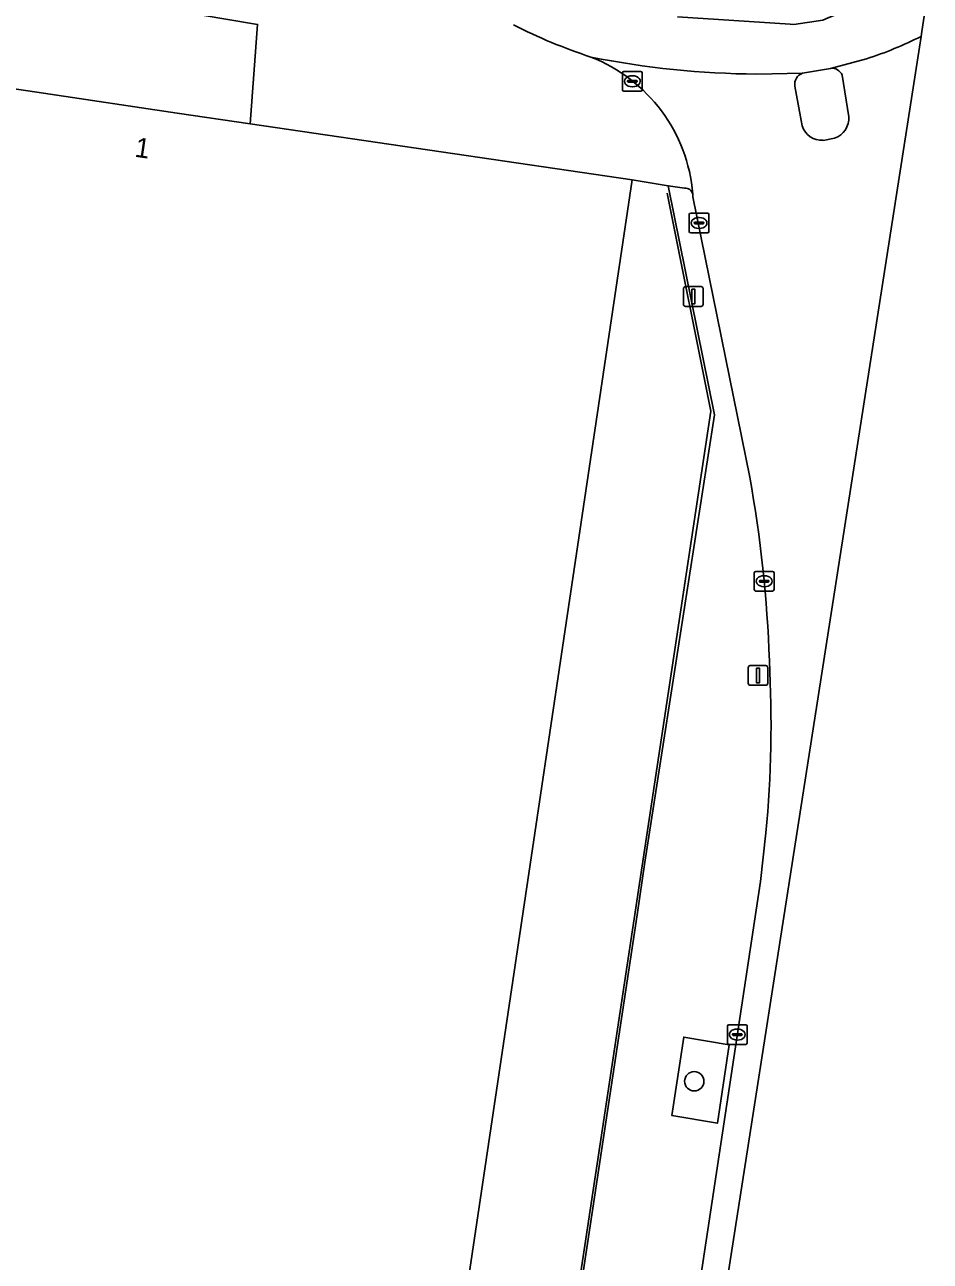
# Model space of a CAD drawing. Extents: x 163008 to 163854, y 382777 to 383982.
# Drawn here: x 163664.1 to 163710.1, y 382884.8 to 382947.5 of the extents above; entities that cross this region are included whole.
import ezdxf

# ---------------------------------------------------------------- set-up
doc = ezdxf.new("R2010")
doc.units = 0
for name, color, linetype in [('IMGEO_Boom', 7, 'Continuous'), ('IMGEO_Erf', 7, 'Continuous'), ('IMGEO_Fietspad_gesloten', 7, 'Continuous'), ('IMGEO_Groenvoorziening', 7, 'Continuous'), ('IMGEO_Hek', 7, 'Continuous'), ('IMGEO_Kolk', 7, 'Continuous'), ('IMGEO_Lichtmast', 7, 'Continuous'), ('IMGEO_Pand', 7, 'Continuous'), ('IMGEO_Pand_nummerreeks', 7, 'Continuous'), ('IMGEO_Rijbaan_lokaal_gesloten', 7, 'Continuous'), ('IMGEO_Verkeerseiland_gesloten', 7, 'Continuous'), ('IMGEO_Voetpad_open', 7, 'Continuous')]:
    doc.layers.add(name, color=color, linetype=linetype)

msp = doc.modelspace()

# ---------------------------------------------------------------- linework, layer by layer
at = {"layer": 'IMGEO_Boom'}
msp.add_circle((163698.093, 382893.932), 0.489, dxfattribs=at)
at = {"layer": 'IMGEO_Erf'}
msp.add_lwpolyline([(163660.069, 382944.782), (163665.094, 382944.032), (163671.874, 382943.02), (163675.573, 382942.478), (163675.95, 382947.517), (163662.801, 382949.742)], dxfattribs=at)
msp.add_lwpolyline([(163695.192, 382902.377), (163695.593, 382905.038), (163699.126, 382927.727), (163696.771, 382939.336), (163694.944, 382939.641), (163686.07, 382880.075), (163680.173, 382841.91), (163682.212, 382846.916), (163682.423, 382846.829), (163682.563, 382846.772), (163689.287, 382863.234)], close=True, dxfattribs=at)
at = {"layer": 'IMGEO_Fietspad_gesloten'}
for points in [[(163709.595, 382946.913), (163709.634, 382947.163), (163710.061, 382949.969), (163710.061, 382949.969), (163709.813, 382949.868), (163704.879, 382947.85), (163704.615, 382947.741), (163703.136, 382947.515), (163702.959, 382947.527), (163697.238, 382947.909)], [(163701.26, 382945.001), (163703.586, 382945.042), (163705.005, 382945.29), (163706.832, 382945.777)]]:
    msp.add_lwpolyline(points, dxfattribs=at)
for centre, radius, start, end in [((163701.319, 382971.705), 27.193, 242.87549, 251.85164), ((163701.11, 382963.624), 18.742, 287.77776, 296.92025), ((163701.592, 382989.658), 44.659, 258.70975, 269.57373)]:
    msp.add_arc(centre, radius, start, end, dxfattribs=at)
at = {"layer": 'IMGEO_Groenvoorziening'}
msp.add_lwpolyline([(163699.86, 382895.783), (163697.558, 382896.177), (163696.959, 382892.195), (163699.266, 382891.807)], close=True, dxfattribs=at)
at = {"layer": 'IMGEO_Hek'}
msp.add_lwpolyline([(163696.717, 382938.956), (163698.941, 382927.911), (163689.192, 382863.442), (163682.423, 382846.829)], dxfattribs=at)
at = {"layer": 'IMGEO_Kolk'}
for p, q in [((163694.453, 382944.208), (163694.453, 382945.06)), ((163694.528, 382945.134), (163695.38, 382945.134)), ((163694.755, 382944.677), (163695.153, 382944.677)), ((163694.941, 382944.914), (163694.966, 382944.914)), ((163695.454, 382945.06), (163695.454, 382944.208)), ((163695.38, 382944.134), (163694.528, 382944.134)), ((163694.712, 382944.628), (163694.712, 382944.64)), ((163695.15, 382944.591), (163694.752, 382944.591)), ((163694.964, 382944.354), (163694.939, 382944.354)), ((163695.196, 382944.64), (163695.196, 382944.628)), ((163697.837, 382937.024), (163697.837, 382937.876)), ((163697.912, 382937.95), (163698.764, 382937.95)), ((163698.838, 382937.876), (163698.838, 382937.024)), ((163698.096, 382937.444), (163698.096, 382937.456)), ((163698.534, 382937.407), (163698.136, 382937.407)), ((163698.139, 382937.493), (163698.537, 382937.493)), ((163698.348, 382937.17), (163698.323, 382937.17)), ((163698.325, 382937.73), (163698.35, 382937.73)), ((163698.58, 382937.456), (163698.58, 382937.444)), ((163698.764, 382936.95), (163697.912, 382936.95)), ((163701.139, 382918.861), (163701.139, 382919.713)), ((163701.214, 382919.787), (163702.066, 382919.787)), ((163702.14, 382919.713), (163702.14, 382918.861)), ((163701.398, 382919.281), (163701.398, 382919.293)), ((163701.836, 382919.244), (163701.438, 382919.244)), ((163701.441, 382919.33), (163701.839, 382919.33)), ((163701.65, 382919.007), (163701.625, 382919.007)), ((163701.627, 382919.567), (163701.652, 382919.567)), ((163701.882, 382919.293), (163701.882, 382919.281)), ((163702.066, 382918.787), (163701.214, 382918.787)), ((163699.775, 382895.875), (163699.775, 382896.727)), ((163699.85, 382896.801), (163700.702, 382896.801)), ((163700.263, 382896.581), (163700.288, 382896.581)), ((163700.776, 382896.727), (163700.776, 382895.875)), ((163700.702, 382895.801), (163699.85, 382895.801)), ((163700.034, 382896.295), (163700.034, 382896.307)), ((163700.472, 382896.258), (163700.074, 382896.258)), ((163700.077, 382896.344), (163700.475, 382896.344)), ((163700.286, 382896.021), (163700.261, 382896.021)), ((163700.518, 382896.307), (163700.518, 382896.295))]:
    msp.add_line(p, q, dxfattribs=at)
for points in [[(163694.453, 382944.208), (163694.453, 382945.06)], [(163694.528, 382945.134), (163695.38, 382945.134)], [(163695.454, 382945.06), (163695.454, 382944.208)], [(163695.38, 382944.134), (163694.528, 382944.134)], [(163697.837, 382937.024), (163697.837, 382937.876)], [(163697.912, 382937.95), (163698.764, 382937.95)], [(163698.838, 382937.876), (163698.838, 382937.024)], [(163698.764, 382936.95), (163697.912, 382936.95)], [(163701.139, 382918.861), (163701.139, 382919.713)], [(163701.214, 382919.787), (163702.066, 382919.787)], [(163702.14, 382919.713), (163702.14, 382918.861)], [(163702.066, 382918.787), (163701.214, 382918.787)], [(163699.775, 382895.875), (163699.775, 382896.727)], [(163699.85, 382896.801), (163700.702, 382896.801)], [(163700.776, 382896.727), (163700.776, 382895.875)], [(163700.702, 382895.801), (163699.85, 382895.801)]]:
    msp.add_lwpolyline(points, dxfattribs=at)
for centre, radius, start, end in [((163694.53, 382945.058), 0.0765, 91.55205, 178.44795), ((163694.53, 382945.058), 0.0765, 91.55205, 178.44795), ((163694.752, 382944.637), 0.0403, 85.87752, 175.75265), ((163695.157, 382944.639), 0.0386, 1.73085, 96.63898), ((163695.378, 382945.058), 0.0765, 1.55205, 88.44795), ((163695.378, 382945.058), 0.0765, 1.55205, 88.44795), ((163694.53, 382944.21), 0.0765, 181.55205, 268.44795), ((163694.53, 382944.21), 0.0765, 181.55205, 268.44795), ((163694.749, 382944.627), 0.0366, 178.93798, 274.71019), ((163695.153, 382944.634), 0.043, 264.86636, 352.45326), ((163695.378, 382944.21), 0.0765, 271.55205, 358.44795), ((163695.378, 382944.21), 0.0765, 271.55205, 358.44795), ((163697.914, 382937.874), 0.0765, 91.55205, 178.44795), ((163697.914, 382937.874), 0.0765, 91.55205, 178.44795), ((163698.762, 382937.874), 0.0765, 1.55205, 88.44795), ((163698.762, 382937.874), 0.0765, 1.55205, 88.44795), ((163698.136, 382937.453), 0.0403, 85.87752, 175.75265), ((163698.133, 382937.443), 0.0366, 178.93798, 274.71019), ((163698.537, 382937.45), 0.043, 264.86636, 352.45326), ((163698.541, 382937.455), 0.0386, 1.73085, 96.63898), ((163697.914, 382937.026), 0.0765, 181.55205, 268.44795), ((163697.914, 382937.026), 0.0765, 181.55205, 268.44795), ((163698.762, 382937.026), 0.0765, 271.55205, 358.44795), ((163698.762, 382937.026), 0.0765, 271.55205, 358.44795), ((163701.216, 382919.711), 0.0765, 91.55205, 178.44795), ((163701.216, 382919.711), 0.0765, 91.55205, 178.44795), ((163702.064, 382919.711), 0.0765, 1.55205, 88.44795), ((163702.064, 382919.711), 0.0765, 1.55205, 88.44795), ((163701.438, 382919.29), 0.0403, 85.87752, 175.75265), ((163701.435, 382919.28), 0.0366, 178.93798, 274.71019), ((163701.839, 382919.287), 0.043, 264.86636, 352.45326), ((163701.843, 382919.292), 0.0386, 1.73085, 96.63898), ((163701.216, 382918.863), 0.0765, 181.55205, 268.44795), ((163701.216, 382918.863), 0.0765, 181.55205, 268.44795), ((163702.064, 382918.863), 0.0765, 271.55205, 358.44795), ((163702.064, 382918.863), 0.0765, 271.55205, 358.44795), ((163699.852, 382896.725), 0.0765, 91.55205, 178.44795), ((163699.852, 382896.725), 0.0765, 91.55205, 178.44795), ((163700.7, 382896.725), 0.0765, 1.55205, 88.44795), ((163700.7, 382896.725), 0.0765, 1.55205, 88.44795), ((163699.852, 382895.877), 0.0765, 181.55205, 268.44795), ((163699.852, 382895.877), 0.0765, 181.55205, 268.44795), ((163700.074, 382896.304), 0.0403, 85.87752, 175.75265), ((163700.071, 382896.294), 0.0366, 178.93798, 274.71019), ((163700.475, 382896.301), 0.043, 264.86636, 352.45326), ((163700.479, 382896.306), 0.0386, 1.73085, 96.63898), ((163700.7, 382895.877), 0.0765, 271.55205, 358.44795), ((163700.7, 382895.877), 0.0765, 271.55205, 358.44795)]:
    msp.add_arc(centre, radius, start, end, dxfattribs=at)
for centre, major_axis, ratio, start_param, end_param in [((163694.94, 382944.634), (-0.387, 0.002), 0.722429, 4.712389, 7.853982), ((163694.965, 382944.634), (-0.39, 0.002), 0.717154, 1.570796, 4.712389), ((163698.324, 382937.45), (-0.387, 0.002), 0.722429, 4.712389, 7.853982), ((163698.349, 382937.45), (-0.39, 0.002), 0.717154, 1.570796, 4.712389), ((163701.626, 382919.287), (-0.387, 0.002), 0.722429, 4.712389, 7.853982), ((163701.651, 382919.287), (-0.39, 0.002), 0.717154, 1.570796, 4.712389), ((163700.262, 382896.301), (-0.387, 0.002), 0.722429, 4.712389, 7.853982), ((163700.287, 382896.301), (-0.39, 0.002), 0.717154, 1.570796, 4.712389)]:
    msp.add_ellipse(centre, major_axis=major_axis, ratio=ratio, start_param=start_param, end_param=end_param, dxfattribs=at)
at = {"layer": 'IMGEO_Lichtmast'}
for p, q in [((163697.547, 382933.323), (163697.547, 382934.123)), ((163697.547, 382934.123), (163697.547, 382933.323)), ((163697.647, 382934.223), (163698.437, 382934.223)), ((163698.437, 382934.223), (163697.647, 382934.223)), ((163698.537, 382934.123), (163698.537, 382933.323)), ((163698.537, 382933.323), (163698.537, 382934.123)), ((163698.437, 382933.223), (163697.647, 382933.223)), ((163697.647, 382933.223), (163698.437, 382933.223)), ((163700.83, 382914.109), (163700.83, 382914.909)), ((163700.83, 382914.909), (163700.83, 382914.109)), ((163700.93, 382915.009), (163701.72, 382915.009)), ((163701.72, 382915.009), (163700.93, 382915.009)), ((163701.82, 382914.909), (163701.82, 382914.109)), ((163701.82, 382914.109), (163701.82, 382914.909)), ((163701.72, 382914.009), (163700.93, 382914.009)), ((163700.93, 382914.009), (163701.72, 382914.009))]:
    msp.add_line(p, q, dxfattribs=at)
for points in [[(163697.967, 382934.098), (163698.117, 382934.098), (163698.117, 382933.348), (163697.967, 382933.348), (163697.967, 382934.098)], [(163701.25, 382914.884), (163701.4, 382914.884), (163701.4, 382914.134), (163701.25, 382914.134), (163701.25, 382914.884)]]:
    msp.add_lwpolyline(points, dxfattribs=at)
for centre, start, end in [((163697.647, 382934.123), 90, 180), ((163697.647, 382934.123), 90, 180), ((163698.437, 382934.123), 0, 90), ((163698.437, 382934.123), 360, 90), ((163697.647, 382933.323), 180, 270), ((163697.647, 382933.323), 180, 270), ((163698.437, 382933.323), 270, 0), ((163698.437, 382933.323), 270, 0), ((163700.93, 382914.909), 90, 180), ((163700.93, 382914.909), 90, 180), ((163701.72, 382914.909), 0, 90), ((163701.72, 382914.909), 360, 90), ((163700.93, 382914.109), 180, 270), ((163700.93, 382914.109), 180, 270), ((163701.72, 382914.109), 270, 0), ((163701.72, 382914.109), 270, 0)]:
    msp.add_arc(centre, 0.1, start, end, dxfattribs=at)
at = {"layer": 'IMGEO_Pand'}
msp.add_lwpolyline([(163686.07, 382880.075), (163694.944, 382939.641), (163675.573, 382942.478), (163671.874, 382943.02), (163665.094, 382944.032), (163660.069, 382944.782), (163660.676, 382948.848), (163657.213, 382949.356), (163654.375, 382948.97), (163653.887, 382945.706), (163642.513, 382947.403), (163641.775, 382942.458), (163633.371, 382886.155), (163632.813, 382886.325), (163623.367, 382823.699)], dxfattribs=at)
at = {"layer": 'IMGEO_Rijbaan_lokaal_gesloten'}
for points in [[(163689.122, 382815.698), (163709.595, 382946.913)], [(163706.832, 382945.777), (163705.005, 382945.29)], [(163703.586, 382945.042), (163701.26, 382945.001)], [(163705.595, 382944.948), (163705.928, 382942.837)], [(163703.565, 382942.375), (163703.194, 382944.393)], [(163705.211, 382941.751), (163704.633, 382941.64)], [(163698.019, 382938.918), (163698.029, 382938.773), (163700.907, 382924.565)], [(163701.727, 382906.524), (163701.446, 382904.066), (163697.437, 382877.464), (163695.639, 382865.633), (163690.842, 382833.785), (163688.151, 382815.838), (163689.122, 382815.698), (163689.122, 382815.698)]]:
    msp.add_lwpolyline(points, dxfattribs=at)
for centre, radius, start, end in [((163701.11, 382963.624), 18.742, 287.77776, 296.92025), ((163701.592, 382989.658), 44.659, 258.70975, 269.57373), ((163689.872, 382938.251), 8.175, 4.68126, 68.64034), ((163705.077, 382944.734), 0.561, 22.4441, 97.3575), ((163703.777, 382944.484), 0.59, 108.87018, 188.86535), ((163704.869, 382942.757), 1.062, 288.79794, 4.3348), ((163704.573, 382942.697), 1.058, 197.69121, 273.23712), ((163637.696, 382913.095), 64.243, 1.92302, 10.28452), ((163641.643, 382912.101), 60.342, 354.697, 2.99231)]:
    msp.add_arc(centre, radius, start, end, dxfattribs=at)
at = {"layer": 'IMGEO_Verkeerseiland_gesloten'}
for points in [[(163705.005, 382945.29), (163703.586, 382945.042)], [(163705.928, 382942.837), (163705.595, 382944.948)], [(163703.194, 382944.393), (163703.565, 382942.375)], [(163704.633, 382941.64), (163705.211, 382941.751)]]:
    msp.add_lwpolyline(points, dxfattribs=at)
for centre, radius, start, end in [((163705.077, 382944.734), 0.561, 22.4441, 97.3575), ((163703.777, 382944.484), 0.59, 108.87018, 188.86535), ((163704.869, 382942.757), 1.062, 288.79794, 4.3348), ((163704.573, 382942.697), 1.058, 197.69121, 273.23712)]:
    msp.add_arc(centre, radius, start, end, dxfattribs=at)
at = {"layer": 'IMGEO_Voetpad_open'}
for points in [[(163679.228, 382950.224), (163669.011, 382951.747), (163650.997, 382961.099), (163647.404, 382960.974), (163647.115, 382959.08), (163657.804, 382953.488), (163657.373, 382951.433), (163654.013, 382951.942), (163654.325, 382954.019), (163646.511, 382955.211), (163646.06, 382952.245), (163657.187, 382950.546), (163662.801, 382949.742), (163675.95, 382947.517), (163675.573, 382942.478), (163694.944, 382939.641), (163696.771, 382939.336), (163697.597, 382939.219)], [(163697.597, 382939.219), (163696.771, 382939.336), (163699.126, 382927.727), (163695.593, 382905.038), (163695.192, 382902.377), (163689.287, 382863.234), (163691.671, 382868.838)], [(163700.907, 382924.565), (163698.029, 382938.773), (163698.019, 382938.918)], [(163693.223, 382871.72), (163695.076, 382874.475), (163697.437, 382877.464), (163701.446, 382904.066), (163701.727, 382906.524)]]:
    msp.add_lwpolyline(points, dxfattribs=at)
msp.add_lwpolyline([(163699.266, 382891.807), (163696.959, 382892.195), (163697.558, 382896.177), (163699.86, 382895.783)], close=True, dxfattribs=at)
for centre, radius, start, end in [((163701.319, 382971.705), 27.193, 242.87549, 251.85164), ((163689.872, 382938.251), 8.175, 4.68126, 68.64034), ((163697.628, 382938.817), 0.404, 14.54501, 94.45673), ((163697.628, 382938.817), 0.404, 14.54501, 94.45673), ((163637.696, 382913.095), 64.243, 1.92302, 10.28452), ((163641.643, 382912.101), 60.342, 354.697, 2.99231)]:
    msp.add_arc(centre, radius, start, end, dxfattribs=at)

# ---------------------------------------------------------------- texts
at = {"layer": 'IMGEO_Pand_nummerreeks'}
msp.add_text('1', height=1, rotation=351.66919, dxfattribs=at).set_placement((163669.682, 382940.815))

doc.saveas('drawing.dxf')
